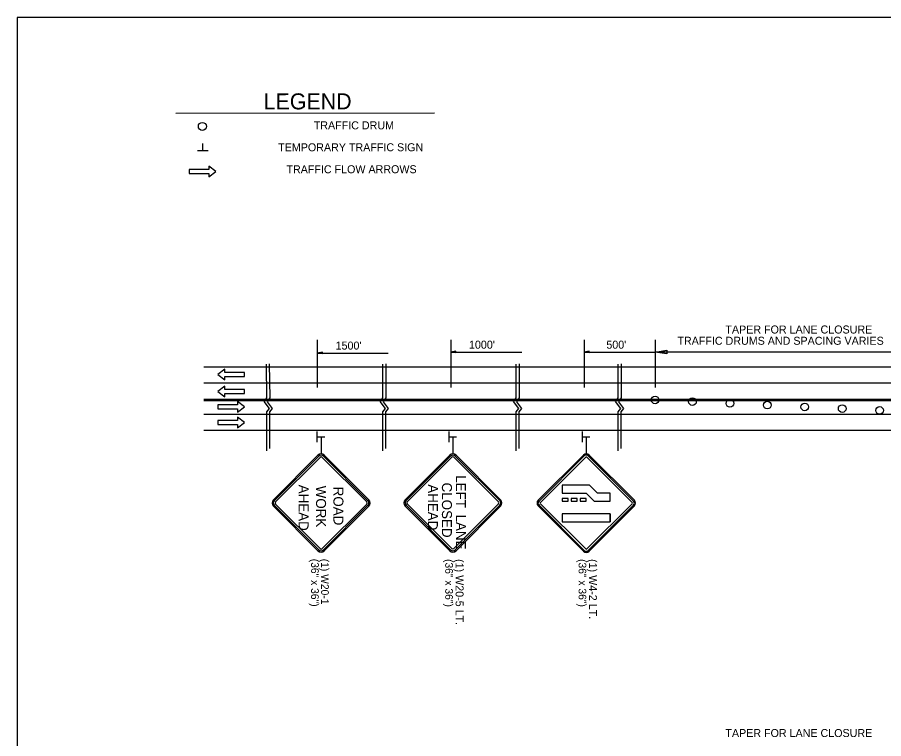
# Model space of a CAD drawing. Extents: x 1930579 to 1938013, y 596452 to 597673.
# Drawn here: x 1936313 to 1936962, y 597133 to 597673 of the extents above; entities that cross this region are included whole.
import ezdxf

# ---------------------------------------------------------------- set-up
doc = ezdxf.new("R2010")
doc.units = 0
for name, color, linetype in [('Default', 7, 'Continuous'), ('P_TC_Signs_Permanent', 7, 'Continuous'), ('P_TC_Signs_Temporary', 7, 'Continuous'), ('R_Border', 7, 'Continuous'), ('R_MOT', 7, 'Continuous'), ('R_Striping', 7, 'Continuous'), ('S_AREA_CALC', 7, 'Continuous')]:
    doc.layers.add(name, color=color, linetype=linetype)

msp = doc.modelspace()

# ---------------------------------------------------------------- linework, layer by layer
at = {"layer": 'Default'}
for p, q in [((1936537.79, 597431.71), (1936537.79, 597395.8)), ((1936637.79, 597431.71), (1936637.79, 597395.8)), ((1936737.79, 597431.71), (1936737.79, 597395.8)), ((1936791.02, 597431.71), (1936791.02, 597395.8)), ((1936541.62, 597422.3), (1936537.79, 597421.72)), ((1936537.79, 597421.72), (1936591.02, 597421.72)), ((1936541.62, 597421.15), (1936537.79, 597421.72)), ((1936541.62, 597422.2), (1936538.43, 597421.72)), ((1936541.62, 597421.24), (1936538.43, 597421.72)), ((1936541.62, 597422.1), (1936539.09, 597421.72)), ((1936541.62, 597421.34), (1936539.09, 597421.72)), ((1936541.62, 597422.01), (1936539.73, 597421.72)), ((1936541.62, 597421.44), (1936539.73, 597421.72)), ((1936541.62, 597421.91), (1936540.37, 597421.72)), ((1936541.62, 597421.54), (1936540.37, 597421.72)), ((1936541.62, 597421.81), (1936541.01, 597421.72)), ((1936541.62, 597421.63), (1936541.01, 597421.72)), ((1936541.62, 597421.15), (1936541.62, 597422.3)), ((1936641.62, 597422.98), (1936637.79, 597422.4)), ((1936637.79, 597422.4), (1936691.02, 597422.4)), ((1936641.62, 597421.83), (1936637.79, 597422.4)), ((1936641.62, 597422.88), (1936638.43, 597422.4)), ((1936641.62, 597421.92), (1936638.43, 597422.4)), ((1936641.62, 597422.78), (1936639.09, 597422.4)), ((1936641.62, 597422.02), (1936639.09, 597422.4)), ((1936641.62, 597422.69), (1936639.73, 597422.4)), ((1936641.62, 597422.12), (1936639.73, 597422.4)), ((1936641.62, 597422.59), (1936640.37, 597422.4)), ((1936641.62, 597422.22), (1936640.37, 597422.4)), ((1936641.62, 597422.49), (1936641.01, 597422.4)), ((1936641.62, 597422.31), (1936641.01, 597422.4)), ((1936641.62, 597421.83), (1936641.62, 597422.98)), ((1936741.62, 597422.98), (1936737.79, 597422.4)), ((1936737.79, 597422.4), (1936791.02, 597422.4)), ((1936741.62, 597421.83), (1936737.79, 597422.4)), ((1936741.62, 597422.88), (1936738.43, 597422.4)), ((1936741.62, 597421.92), (1936738.43, 597422.4)), ((1936741.62, 597422.78), (1936739.09, 597422.4)), ((1936741.62, 597422.02), (1936739.09, 597422.4)), ((1936741.62, 597422.69), (1936739.73, 597422.4)), ((1936741.62, 597422.12), (1936739.73, 597422.4)), ((1936741.62, 597422.59), (1936740.37, 597422.4)), ((1936741.62, 597422.22), (1936740.37, 597422.4)), ((1936741.62, 597422.49), (1936741.01, 597422.4)), ((1936741.62, 597422.31), (1936741.01, 597422.4)), ((1936741.62, 597421.83), (1936741.62, 597422.98)), ((1936791.02, 597422.4), (1936799.89, 597423.73)), ((1937015.53, 597422.4), (1936791.02, 597422.4)), ((1936799.89, 597421.07), (1936791.02, 597422.4)), ((1936799.89, 597423.73), (1936799.89, 597421.07)), ((1937804.86, 597411.17), (1936452.69, 597411.17)), ((1937804.86, 597399.17), (1936452.69, 597399.17)), ((1937804.86, 597386.94), (1936452.69, 597386.94)), ((1937804.86, 597385.79), (1936452.69, 597385.79)), ((1937804.86, 597375.6), (1936452.69, 597375.6)), ((1937804.86, 597363.6), (1936452.69, 597363.6)), ((1936537.79, 597355), (1936537.79, 597362.98)), ((1936636.62, 597354.95), (1936636.62, 597362.93)), ((1936736.62, 597354.95), (1936736.62, 597362.93)), ((1936537.91, 597358.97), (1936543.36, 597358.97)), ((1936636.74, 597358.92), (1936642.18, 597358.92)), ((1936736.74, 597358.92), (1936742.18, 597358.92))]:
    msp.add_line(p, q, dxfattribs=at)
for points in [[(1936499.33, 597413.45), (1936499.72, 597388.21), (1936497.77, 597385.31), (1936501.57, 597380.12), (1936499.57, 597377.72), (1936499.56, 597348.37)], [(1936501.73, 597413.68), (1936502.12, 597388.11), (1936500.17, 597385.21), (1936503.96, 597380.02), (1936501.96, 597377.62), (1936501.96, 597350.06)], [(1936586.69, 597413.45), (1936586.69, 597388.21), (1936584.74, 597385.31), (1936588.54, 597380.12), (1936586.54, 597377.72), (1936586.54, 597348.37)], [(1936589.09, 597413.68), (1936589.09, 597388.11), (1936587.14, 597385.21), (1936590.94, 597380.02), (1936588.94, 597377.62), (1936588.94, 597350.06)], [(1936686.69, 597413.45), (1936686.69, 597388.21), (1936684.74, 597385.31), (1936688.54, 597380.12), (1936686.54, 597377.72), (1936686.54, 597348.37)], [(1936689.09, 597413.68), (1936689.09, 597388.11), (1936687.14, 597385.21), (1936690.94, 597380.02), (1936688.94, 597377.62), (1936688.94, 597350.06)], [(1936763.16, 597413.45), (1936763.16, 597388.21), (1936761.21, 597385.31), (1936765.01, 597380.12), (1936763.01, 597377.72), (1936763, 597348.37)], [(1936765.56, 597413.68), (1936765.56, 597388.11), (1936763.61, 597385.21), (1936767.4, 597380.02), (1936765.41, 597377.62), (1936765.4, 597350.06)]]:
    msp.add_lwpolyline(points, dxfattribs=at)
for centre, radius in [((1936451.57, 597591.57), 3), ((1936791.02, 597386.59), 2.87), ((1936819.09, 597385.28), 2.87), ((1936847.15, 597383.97), 2.87), ((1936875.21, 597382.65), 2.87), ((1936903.28, 597381.34), 2.87), ((1936931.34, 597380.03), 2.87), ((1936959.4, 597378.71), 2.87)]:
    msp.add_circle(centre, radius, dxfattribs=at)
at = {"layer": 'P_TC_Signs_Permanent'}
for p, q in [((1936737.34, 597345.24), (1936703.4, 597311.3)), ((1936775.52, 597311.3), (1936741.58, 597345.24)), ((1936703.4, 597307.05), (1936737.34, 597273.11)), ((1936757.46, 597301.13), (1936757.46, 597295.13))]:
    msp.add_line(p, q, dxfattribs=at)
for points in [[(1936704.03, 597310.66), (1936737.97, 597344.6)], [(1936739.04, 597343.54), (1936705.09, 597309.6)], [(1936773.82, 597309.6), (1936739.88, 597343.54)], [(1936740.94, 597344.6), (1936774.89, 597310.66)], [(1936737.97, 597273.75), (1936704.03, 597307.69)], [(1936705.09, 597308.75), (1936739.04, 597274.81)], [(1936739.88, 597274.81), (1936773.82, 597308.75)], [(1936774.89, 597307.69), (1936740.94, 597273.75)], [(1936741.58, 597273.11), (1936758.55, 597290.08), (1936775.52, 597307.05)]]:
    msp.add_lwpolyline(points, dxfattribs=at)
for points in [[(1936721.46, 597322.67), (1936721.46, 597316.67), (1936739.46, 597316.67), (1936745.46, 597310.67), (1936757.46, 597310.67), (1936757.46, 597316.67), (1936747.94, 597316.67), (1936741.94, 597322.67)], [(1936721.46, 597312.77), (1936721.46, 597310.67), (1936725.96, 597310.67), (1936725.96, 597312.77)], [(1936728.21, 597312.77), (1936728.21, 597310.67), (1936732.71, 597310.67), (1936732.71, 597312.77)], [(1936734.96, 597312.77), (1936734.96, 597310.67), (1936739.46, 597310.67), (1936739.46, 597312.77)], [(1936721.46, 597301.13), (1936721.46, 597295.13), (1936757.46, 597295.13), (1936757.46, 597301.13)]]:
    msp.add_lwpolyline(points, close=True, dxfattribs=at)
for centre, radius, start, end in [((1936739.46, 597343.12), 3, 45, 135), ((1936739.46, 597343.12), 2.1, 45, 135), ((1936739.46, 597343.12), 0.6, 45, 135), ((1936705.52, 597309.17), 3, 135, 225), ((1936773.4, 597309.17), 3, 315, 45), ((1936705.52, 597309.17), 2.1, 135, 225), ((1936705.52, 597309.17), 0.6, 135, 225), ((1936773.4, 597309.17), 0.6, 315, 45), ((1936773.4, 597309.17), 2.1, 315, 45), ((1936739.46, 597275.23), 3, 225, 315), ((1936739.46, 597275.23), 2.1, 225, 315), ((1936739.46, 597275.23), 0.6, 225, 315)]:
    msp.add_arc(centre, radius, start, end, dxfattribs=at)
at = {"layer": 'P_TC_Signs_Temporary'}
for p, q in [((1936504.84, 597311.64), (1936538.25, 597345.05)), ((1936505.5, 597310.98), (1936538.91, 597344.39)), ((1936506.43, 597310.05), (1936539.84, 597343.46)), ((1936541.43, 597343.46), (1936574.84, 597310.05)), ((1936542.36, 597344.39), (1936575.77, 597310.98)), ((1936543.02, 597345.05), (1936576.43, 597311.64)), ((1936603.66, 597311.72), (1936637.07, 597345.13)), ((1936604.33, 597311.05), (1936637.74, 597344.46)), ((1936605.25, 597310.13), (1936638.66, 597343.54)), ((1936640.26, 597343.54), (1936673.67, 597310.13)), ((1936641.18, 597344.46), (1936674.59, 597311.05)), ((1936641.85, 597345.13), (1936675.26, 597311.72)), ((1936538.25, 597273.46), (1936504.84, 597306.87)), ((1936538.91, 597274.12), (1936505.5, 597307.53)), ((1936539.84, 597275.05), (1936506.43, 597308.46)), ((1936574.84, 597308.46), (1936541.43, 597275.05)), ((1936575.77, 597307.53), (1936542.36, 597274.12)), ((1936576.43, 597306.87), (1936543.02, 597273.46)), ((1936637.07, 597273.53), (1936603.66, 597306.94)), ((1936637.74, 597274.2), (1936604.33, 597307.61)), ((1936638.66, 597275.12), (1936605.25, 597308.53)), ((1936673.67, 597308.53), (1936640.26, 597275.12)), ((1936674.59, 597307.61), (1936641.18, 597274.2)), ((1936675.26, 597306.94), (1936641.85, 597273.53))]:
    msp.add_line(p, q, dxfattribs=at)
for centre, radius, start, end in [((1936540.63, 597342.67), 3.38, 45, 135), ((1936540.63, 597342.67), 2.44, 45, 135), ((1936540.63, 597342.67), 1.12, 45, 135), ((1936639.46, 597342.74), 3.38, 45, 135), ((1936639.46, 597342.74), 2.44, 45, 135), ((1936639.46, 597342.74), 1.12, 45, 135), ((1936507.22, 597309.26), 3.38, 135, 225), ((1936507.22, 597309.26), 2.44, 135, 225), ((1936574.04, 597309.26), 2.44, 315, 45), ((1936574.04, 597309.26), 3.38, 315, 45), ((1936606.05, 597309.33), 3.38, 135, 225), ((1936606.05, 597309.33), 2.44, 135, 225), ((1936672.87, 597309.33), 2.44, 315, 45), ((1936672.87, 597309.33), 3.38, 315, 45), ((1936507.22, 597309.26), 1.13, 135, 225), ((1936574.04, 597309.26), 1.13, 315, 45), ((1936606.05, 597309.33), 1.13, 135, 225), ((1936672.87, 597309.33), 1.13, 315, 45), ((1936540.63, 597275.85), 3.38, 225, 315), ((1936540.63, 597275.85), 2.44, 225, 315), ((1936540.63, 597275.85), 1.12, 225, 315), ((1936639.46, 597275.92), 3.38, 225, 315), ((1936639.46, 597275.92), 2.44, 225, 315), ((1936639.46, 597275.92), 1.12, 225, 315)]:
    msp.add_arc(centre, radius, start, end, dxfattribs=at)
at = {"layer": 'R_Border'}
for p, q in [((1936431.79, 597601.6), (1936625.71, 597601.73)), ((1936451.95, 597573.4), (1936451.95, 597578.86)), ((1936455.93, 597573.29), (1936447.93, 597573.28)), ((1936540.63, 597358.97), (1936540.63, 597346.04)), ((1936639.46, 597358.91), (1936639.46, 597346.12)), ((1936739.46, 597358.91), (1936739.46, 597346.12))]:
    msp.add_line(p, q, dxfattribs=at)
at = {"layer": 'R_MOT'}
msp.add_lwpolyline([(1936456.44, 597553.89), (1936461.63, 597557.89), (1936456.44, 597561.89), (1936456.44, 597559.39), (1936441.73, 597559.38), (1936441.73, 597556.38), (1936456.44, 597556.39)], close=True, dxfattribs=at)
at = {"layer": 'R_Striping'}
for points in [[(1936468.42, 597409.53), (1936463.23, 597405.53), (1936468.42, 597401.53), (1936468.42, 597404.03), (1936483.13, 597404.03), (1936483.13, 597407.03), (1936468.42, 597407.03)], [(1936468.42, 597396.9), (1936463.23, 597392.9), (1936468.42, 597388.9), (1936468.42, 597391.4), (1936483.13, 597391.4), (1936483.13, 597394.4), (1936468.42, 597394.4)], [(1936477.94, 597377.39), (1936483.13, 597381.39), (1936477.94, 597385.39), (1936477.94, 597382.89), (1936463.23, 597382.89), (1936463.23, 597379.89), (1936477.94, 597379.89)], [(1936477.94, 597365.61), (1936483.13, 597369.61), (1936477.94, 597373.61), (1936477.94, 597371.11), (1936463.23, 597371.11), (1936463.23, 597368.11), (1936477.94, 597368.11)]]:
    msp.add_lwpolyline(points, close=True, dxfattribs=at)
at = {"layer": 'S_AREA_CALC'}
msp.add_lwpolyline([(1938012.84, 597673.36), (1936312.84, 597673.36), (1936312.84, 596573.37), (1938012.84, 596573.37)], close=True, dxfattribs=at)

# ---------------------------------------------------------------- texts
at = {"layer": 'Default'}
for s, p in [('TAPER FOR LANE CLOSURE', (1936843.77, 597436.34)), ("1500'", (1936551.51, 597424.3)), ("1000'", (1936651.51, 597424.96)), ("500'", (1936754.51, 597424.96)), ('TRAFFIC DRUMS AND SPACING VARIES', (1936807.8, 597427.9)), ('TAPER FOR LANE CLOSURE', (1936843.77, 597133.82))]:
    msp.add_text(s, height=6, rotation=360, dxfattribs=at).set_placement(p)
at = {"layer": 'P_TC_Signs_Temporary'}
for s, p in [('CLOSED', (1936631.21, 597324.58)), ('LEFT\u2002LANE', (1936641.71, 597330.13)), (' AHEAD ', (1936523.8, 597325.8)), ('WORK', (1936536.82, 597322.25)), (' ROAD ', (1936549.85, 597324.28)), (' AHEAD ', (1936620.71, 597326.1))]:
    msp.add_text(s, height=7.5, rotation=270, dxfattribs=at).set_placement(p)
at = {"layer": 'R_Border'}
for s, height, rotation, p in [('LEGEND', 12, 0.03878, (1936497.52, 597604.33)), ('TRAFFIC DRUM', 6, 0.03876, (1936535.11, 597589.37)), ('TEMPORARY TRAFFIC SIGN', 6, 0.03876, (1936508.44, 597572.89)), ('TRAFFIC FLOW ARROWS', 6, 0.03876, (1936514.64, 597556.43)), ('(36" x 36")', 5.76, 270, (1936533.14, 597267.47)), ('(1) W20-1', 5.76, 270, (1936540.63, 597267.47)), ('(36" x 36")', 5.76, 270, (1936633.7, 597267.23)), ('(1) W20-5 LT.', 6, 270, (1936641.47, 597267.23)), ('(36" x 36")', 5.76, 270, (1936733.7, 597267.23)), ('(1) W4-2 LT.', 6, 270, (1936741.47, 597267.23))]:
    msp.add_text(s, height=height, rotation=rotation, dxfattribs=at).set_placement(p)

doc.saveas('drawing.dxf')
